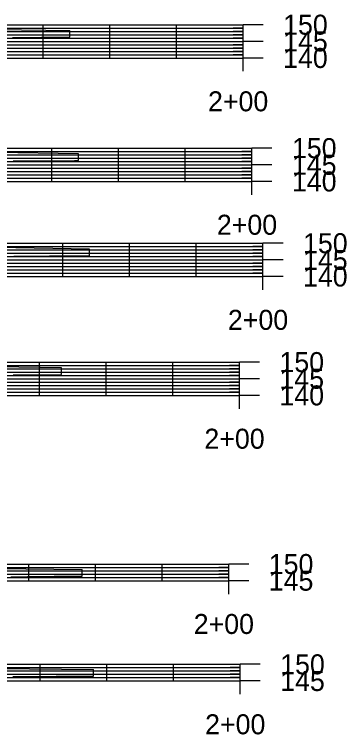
# Model space of a CAD drawing. Extents: x 1556849 to 1559393, y 1802592 to 1804749.
# Drawn here: x 1559293.7 to 1559393.3, y 1802770.9 to 1802987.1 of the extents above; entities that cross this region are included whole.
import ezdxf

# ---------------------------------------------------------------- set-up
doc = ezdxf.new("R2010")
doc.units = 0
for name, color, linetype in [('R_Axis', 7, 'Continuous'), ('R_Axis Annot', 7, 'Continuous'), ('R_Fin Surface', 7, 'Continuous'), ('R_Grid', 7, 'Continuous'), ('R_Proposed Const Limits_Hand', 7, 'Continuous'), ('R_Vert Alg Annot', 7, 'Continuous')]:
    doc.layers.add(name, color=color, linetype=linetype)

msp = doc.modelspace()

# ---------------------------------------------------------------- linework, layer by layer
at = {"layer": 'R_Axis'}
for p, q in [((1559362.3, 1802974.01), (1559362.3, 1802984.01)), ((1559162.3, 1802974.01), (1559362.3, 1802974.01)), ((1559364.95, 1802936.96), (1559364.95, 1802946.96)), ((1559164.95, 1802936.96), (1559364.95, 1802936.96)), ((1559368.27, 1802908.42), (1559368.27, 1802918.42)), ((1559168.27, 1802908.42), (1559368.27, 1802908.42)), ((1559361.2, 1802872.74), (1559361.2, 1802882.74)), ((1559161.2, 1802872.74), (1559361.2, 1802872.74)), ((1559358, 1802817.13), (1559358, 1802822.13)), ((1559158, 1802817.13), (1559358, 1802817.13)), ((1559361.42, 1802787.02), (1559361.42, 1802792.02)), ((1559161.42, 1802787.02), (1559361.42, 1802787.02))]:
    msp.add_line(p, q, dxfattribs=at)
at = {"layer": 'R_Fin Surface'}
for points in [[(1559293.11, 1802980.18), (1559297.22, 1802980.2), (1559298.25, 1802980.2), (1559301.82, 1802980.22), (1559303.39, 1802980.23), (1559305.37, 1802980.24), (1559308.52, 1802980.25), (1559310.3, 1802980.26)], [(1559293.39, 1802943.1), (1559293.76, 1802943.1), (1559294.29, 1802943.11), (1559298.05, 1802943.12), (1559298.58, 1802943.12), (1559302.61, 1802943.14), (1559303.77, 1802943.16), (1559307.17, 1802943.18), (1559308.96, 1802943.19), (1559311.72, 1802943.2), (1559312.95, 1802943.21)], [(1559293.54, 1802914.49), (1559293.72, 1802914.49), (1559295.03, 1802914.51), (1559295.5, 1802914.52), (1559297.02, 1802914.54), (1559298.97, 1802914.56), (1559299.37, 1802914.56), (1559299.88, 1802914.57), (1559304.22, 1802914.59), (1559308.15, 1802914.61), (1559309.47, 1802914.61), (1559312.67, 1802914.62), (1559314.72, 1802914.66), (1559316.27, 1802914.67)], [(1559293.32, 1802878.89), (1559294.14, 1802878.89), (1559294.28, 1802878.89), (1559295.93, 1802878.91), (1559296.09, 1802878.91), (1559296.47, 1802878.91), (1559299.61, 1802878.93), (1559301.02, 1802878.93), (1559304.94, 1802878.95), (1559307.64, 1802878.97), (1559307.85, 1802878.97)], [(1559292.62, 1802818.33), (1559293.99, 1802818.33), (1559297.67, 1802818.39), (1559300.88, 1802818.42), (1559302.72, 1802818.43), (1559305.61, 1802818.46), (1559307.76, 1802818.46), (1559310.23, 1802818.46), (1559312.81, 1802818.48), (1559314, 1802818.5)], [(1559293.25, 1802788.34), (1559294.88, 1802788.34), (1559298.26, 1802788.37), (1559301.39, 1802788.4), (1559303.28, 1802788.4), (1559306.22, 1802788.43), (1559308.29, 1802788.43), (1559311.04, 1802788.45), (1559313.31, 1802788.44), (1559315.71, 1802788.44), (1559317.42, 1802788.46)]]:
    msp.add_lwpolyline(points, dxfattribs=at)
at = {"layer": 'R_Grid'}
for p, q in [((1559162.3, 1802984.01), (1559362.3, 1802984.01)), ((1559162.3, 1802984.01), (1559362.3, 1802984.01)), ((1559302.3, 1802974.01), (1559302.3, 1802984.01)), ((1559322.3, 1802974.01), (1559322.3, 1802984.01)), ((1559342.3, 1802974.01), (1559342.3, 1802984.01)), ((1559368.3, 1802984.01), (1559362.3, 1802984.01)), ((1559368.3, 1802984.01), (1559362.3, 1802984.01)), ((1559162.3, 1802983.01), (1559362.3, 1802983.01)), ((1559162.3, 1802982.01), (1559362.3, 1802982.01)), ((1559362.3, 1802983.01), (1559359.3, 1802983.01)), ((1559362.3, 1802982.01), (1559359.3, 1802982.01)), ((1559162.3, 1802981.01), (1559362.3, 1802981.01)), ((1559162.3, 1802980.01), (1559362.3, 1802980.01)), ((1559362.3, 1802981.01), (1559359.3, 1802981.01)), ((1559362.3, 1802980.01), (1559359.3, 1802980.01)), ((1559162.3, 1802979.01), (1559362.3, 1802979.01)), ((1559162.3, 1802978.01), (1559362.3, 1802978.01)), ((1559362.3, 1802978.01), (1559359.3, 1802978.01)), ((1559368.3, 1802979.01), (1559362.3, 1802979.01)), ((1559162.3, 1802977.01), (1559362.3, 1802977.01)), ((1559162.3, 1802976.01), (1559362.3, 1802976.01)), ((1559362.3, 1802977.01), (1559359.3, 1802977.01)), ((1559362.3, 1802976.01), (1559359.3, 1802976.01)), ((1559162.3, 1802975.01), (1559362.3, 1802975.01)), ((1559362.3, 1802975.01), (1559359.3, 1802975.01)), ((1559368.3, 1802974.01), (1559362.3, 1802974.01)), ((1559362.3, 1802970.01), (1559362.3, 1802974.01)), ((1559164.95, 1802946.96), (1559364.95, 1802946.96)), ((1559164.95, 1802946.96), (1559364.95, 1802946.96)), ((1559164.95, 1802945.96), (1559364.95, 1802945.96)), ((1559164.95, 1802944.96), (1559364.95, 1802944.96)), ((1559304.95, 1802936.96), (1559304.95, 1802946.96)), ((1559324.95, 1802936.96), (1559324.95, 1802946.96)), ((1559344.95, 1802936.96), (1559344.95, 1802946.96)), ((1559364.95, 1802945.96), (1559361.95, 1802945.96)), ((1559364.95, 1802944.96), (1559361.95, 1802944.96)), ((1559370.95, 1802946.96), (1559364.95, 1802946.96)), ((1559370.95, 1802946.96), (1559364.95, 1802946.96)), ((1559164.95, 1802943.96), (1559364.95, 1802943.96)), ((1559164.95, 1802942.96), (1559364.95, 1802942.96)), ((1559364.95, 1802943.96), (1559361.95, 1802943.96)), ((1559364.95, 1802942.96), (1559361.95, 1802942.96)), ((1559164.95, 1802941.96), (1559364.95, 1802941.96)), ((1559164.95, 1802940.96), (1559364.95, 1802940.96)), ((1559364.95, 1802940.96), (1559361.95, 1802940.96)), ((1559370.95, 1802941.96), (1559364.95, 1802941.96)), ((1559164.95, 1802939.96), (1559364.95, 1802939.96)), ((1559164.95, 1802938.96), (1559364.95, 1802938.96)), ((1559364.95, 1802939.96), (1559361.95, 1802939.96)), ((1559364.95, 1802938.96), (1559361.95, 1802938.96)), ((1559164.95, 1802937.96), (1559364.95, 1802937.96)), ((1559364.95, 1802937.96), (1559361.95, 1802937.96)), ((1559370.95, 1802936.96), (1559364.95, 1802936.96)), ((1559364.95, 1802932.96), (1559364.95, 1802936.96)), ((1559168.27, 1802918.42), (1559368.27, 1802918.42)), ((1559168.27, 1802918.42), (1559368.27, 1802918.42)), ((1559168.27, 1802917.42), (1559368.27, 1802917.42)), ((1559308.27, 1802908.42), (1559308.27, 1802918.42)), ((1559328.27, 1802908.42), (1559328.27, 1802918.42)), ((1559348.27, 1802908.42), (1559348.27, 1802918.42)), ((1559368.27, 1802917.42), (1559365.27, 1802917.42)), ((1559374.27, 1802918.42), (1559368.27, 1802918.42)), ((1559374.27, 1802918.42), (1559368.27, 1802918.42)), ((1559168.27, 1802916.42), (1559368.27, 1802916.42)), ((1559168.27, 1802915.42), (1559368.27, 1802915.42)), ((1559368.27, 1802916.42), (1559365.27, 1802916.42)), ((1559368.27, 1802915.42), (1559365.27, 1802915.42)), ((1559168.27, 1802914.42), (1559368.27, 1802914.42)), ((1559168.27, 1802913.42), (1559368.27, 1802913.42)), ((1559168.27, 1802912.42), (1559368.27, 1802912.42)), ((1559368.27, 1802914.42), (1559365.27, 1802914.42)), ((1559368.27, 1802912.42), (1559365.27, 1802912.42)), ((1559374.27, 1802913.42), (1559368.27, 1802913.42)), ((1559168.27, 1802911.42), (1559368.27, 1802911.42)), ((1559168.27, 1802910.42), (1559368.27, 1802910.42)), ((1559368.27, 1802911.42), (1559365.27, 1802911.42)), ((1559368.27, 1802910.42), (1559365.27, 1802910.42)), ((1559168.27, 1802909.42), (1559368.27, 1802909.42)), ((1559368.27, 1802909.42), (1559365.27, 1802909.42)), ((1559374.27, 1802908.42), (1559368.27, 1802908.42)), ((1559368.27, 1802904.42), (1559368.27, 1802908.42)), ((1559161.2, 1802882.74), (1559361.2, 1802882.74)), ((1559161.2, 1802882.74), (1559361.2, 1802882.74)), ((1559301.2, 1802872.74), (1559301.2, 1802882.74)), ((1559321.2, 1802872.74), (1559321.2, 1802882.74)), ((1559341.2, 1802872.74), (1559341.2, 1802882.74)), ((1559367.2, 1802882.74), (1559361.2, 1802882.74)), ((1559367.2, 1802882.74), (1559361.2, 1802882.74)), ((1559161.2, 1802881.74), (1559361.2, 1802881.74)), ((1559161.2, 1802880.74), (1559361.2, 1802880.74)), ((1559361.2, 1802881.74), (1559358.2, 1802881.74)), ((1559361.2, 1802880.74), (1559358.2, 1802880.74)), ((1559161.2, 1802879.74), (1559361.2, 1802879.74)), ((1559161.2, 1802878.74), (1559361.2, 1802878.74)), ((1559361.2, 1802879.74), (1559358.2, 1802879.74)), ((1559361.2, 1802878.74), (1559358.2, 1802878.74)), ((1559161.2, 1802877.74), (1559361.2, 1802877.74)), ((1559161.2, 1802876.74), (1559361.2, 1802876.74)), ((1559161.2, 1802875.74), (1559361.2, 1802875.74)), ((1559361.2, 1802876.74), (1559358.2, 1802876.74)), ((1559361.2, 1802875.74), (1559358.2, 1802875.74)), ((1559367.2, 1802877.74), (1559361.2, 1802877.74)), ((1559161.2, 1802874.74), (1559361.2, 1802874.74)), ((1559161.2, 1802873.74), (1559361.2, 1802873.74)), ((1559361.2, 1802874.74), (1559358.2, 1802874.74)), ((1559361.2, 1802873.74), (1559358.2, 1802873.74)), ((1559367.2, 1802872.74), (1559361.2, 1802872.74)), ((1559361.2, 1802868.74), (1559361.2, 1802872.74)), ((1559158, 1802822.13), (1559358, 1802822.13)), ((1559158, 1802822.13), (1559358, 1802822.13)), ((1559298, 1802817.13), (1559298, 1802822.13)), ((1559318, 1802817.13), (1559318, 1802822.13)), ((1559338, 1802817.13), (1559338, 1802822.13)), ((1559364, 1802822.13), (1559358, 1802822.13)), ((1559364, 1802822.13), (1559358, 1802822.13)), ((1559158, 1802821.13), (1559358, 1802821.13)), ((1559158, 1802820.13), (1559358, 1802820.13)), ((1559358, 1802821.13), (1559355, 1802821.13)), ((1559358, 1802820.13), (1559355, 1802820.13)), ((1559158, 1802819.13), (1559358, 1802819.13)), ((1559158, 1802818.13), (1559358, 1802818.13)), ((1559358, 1802819.13), (1559355, 1802819.13)), ((1559358, 1802818.13), (1559355, 1802818.13)), ((1559364, 1802817.13), (1559358, 1802817.13)), ((1559358, 1802813.13), (1559358, 1802817.13)), ((1559161.42, 1802792.02), (1559361.42, 1802792.02)), ((1559161.42, 1802792.02), (1559361.42, 1802792.02)), ((1559301.42, 1802787.02), (1559301.42, 1802792.02)), ((1559321.42, 1802787.02), (1559321.42, 1802792.02)), ((1559341.42, 1802787.02), (1559341.42, 1802792.02)), ((1559367.42, 1802792.02), (1559361.42, 1802792.02)), ((1559367.42, 1802792.02), (1559361.42, 1802792.02)), ((1559161.42, 1802791.02), (1559361.42, 1802791.02)), ((1559161.42, 1802790.02), (1559361.42, 1802790.02)), ((1559361.42, 1802791.02), (1559358.42, 1802791.02)), ((1559361.42, 1802790.02), (1559358.42, 1802790.02)), ((1559161.42, 1802789.02), (1559361.42, 1802789.02)), ((1559161.42, 1802788.02), (1559361.42, 1802788.02)), ((1559361.42, 1802789.02), (1559358.42, 1802789.02)), ((1559361.42, 1802788.02), (1559358.42, 1802788.02)), ((1559367.42, 1802787.02), (1559361.42, 1802787.02)), ((1559361.42, 1802783.02), (1559361.42, 1802787.02))]:
    msp.add_line(p, q, dxfattribs=at)
at = {"layer": 'R_Proposed Const Limits_Hand'}
for p, q in [((1559162.3, 1802984.64), (1559310.3, 1802982.26)), ((1559310.3, 1802980.26), (1559310.3, 1802982.26)), ((1559312.95, 1802945.21), (1559164.95, 1802947.77)), ((1559312.95, 1802943.21), (1559312.95, 1802945.21)), ((1559316.27, 1802916.67), (1559168.27, 1802919.41)), ((1559316.27, 1802914.67), (1559316.27, 1802916.67)), ((1559307.85, 1802880.97), (1559161.2, 1802883.89)), ((1559307.85, 1802878.97), (1559307.85, 1802880.97)), ((1559158, 1802822.36), (1559314, 1802820.5)), ((1559314, 1802818.5), (1559314, 1802820.5)), ((1559161.42, 1802792.06), (1559317.42, 1802790.46)), ((1559317.42, 1802788.46), (1559317.42, 1802790.46))]:
    msp.add_line(p, q, dxfattribs=at)

# ---------------------------------------------------------------- texts
at = {"layer": 'R_Axis Annot'}
for s, p in [('150', (1559374.3, 1802981.01)), ('150', (1559374.3, 1802981.01)), ('145', (1559374.3, 1802976.01)), ('140', (1559374.3, 1802971.01)), ('150', (1559376.95, 1802943.96)), ('150', (1559376.95, 1802943.96)), ('145', (1559376.95, 1802938.96)), ('140', (1559376.95, 1802933.96)), ('150', (1559380.27, 1802915.42)), ('150', (1559380.27, 1802915.42)), ('145', (1559380.27, 1802910.42)), ('140', (1559380.27, 1802905.42)), ('150', (1559373.2, 1802879.74)), ('150', (1559373.2, 1802879.74)), ('145', (1559373.2, 1802874.74)), ('140', (1559373.2, 1802869.74)), ('150', (1559370, 1802819.13)), ('150', (1559370, 1802819.13)), ('145', (1559370, 1802814.13)), ('150', (1559373.42, 1802789.02)), ('150', (1559373.42, 1802789.02)), ('145', (1559373.42, 1802784.02))]:
    msp.add_text(s, height=6, dxfattribs=at).set_placement(p)
at = {"layer": 'R_Vert Alg Annot'}
for p in [(1559351.78, 1802958.01), (1559354.44, 1802920.96), (1559357.75, 1802892.42), (1559350.69, 1802856.74), (1559347.49, 1802801.13), (1559350.91, 1802771.02)]:
    msp.add_text('2+00', height=6, dxfattribs=at).set_placement(p)

doc.saveas('drawing.dxf')
